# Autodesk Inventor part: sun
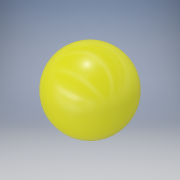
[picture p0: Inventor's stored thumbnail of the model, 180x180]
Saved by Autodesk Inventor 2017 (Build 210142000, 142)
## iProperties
Created: 2016-07
Part Number: sun
Material: Generic
Document SubType Name: Modeling
Designer: Stan
Density: 1 g/cm^3
Appearance: Yellow
Author: Stan
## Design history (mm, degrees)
sketch "Sketch3"
  geometry: L1 (-4.762, -37.801)-(0, -37.801); L2 (0, 38.1)-(0, -37.801); A1 r 38.1 centre (0, 0) between (0, 38.1) and (-4.762, -37.801); 1 further point
  constraints: 4 end point, 2 point on circle, 1 centre point, 1 coincident, 1 horizontal
  dimensions: "d17" = 76.2 diameter of A1
revolve "Revolution2" sketch "Sketch3" stored, may be unused: angle "d19" = 90 deg
sketch "Sketch4"
  geometry: C1 r 1.587 at (0, 0); 1 further point
  constraints: 1 centre point, 1 coincident
  dimensions: "d20" = 3.175 diameter of C1
extrude "Extrusion2" cut sketch "Sketch4" distance "d21" = 6.35; taper "d22" = 0 deg
body "Solid2"
